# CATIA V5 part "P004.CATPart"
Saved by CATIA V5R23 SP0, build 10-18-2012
Part number: P004
Definition: Entretoise
Bounding box of the stored display mesh (mm): x -28 to 28, y -12 to 12, z -12 to 12
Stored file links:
  C:\wamp\www\COURS\CONCEPTION GMP1\TITRE 02-SEMESTRE 2\03-TP7-PRESSE MECANIQUE\eleve\P004.CATPart
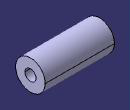
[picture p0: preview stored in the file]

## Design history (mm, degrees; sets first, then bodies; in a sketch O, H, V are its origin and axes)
Body1 (main body)
  Sketch1 on yz-plane, origin (0, 0, 0), H (0, 1, 0), V (0, 0, 1)
    circle A1 centre (0, 0) radius 12
    circle A2 centre (0, 0) radius 4.5
    radius A1 = 12
    radius A2 = 4.5
  Pad1: profile Sketch1, direction (1, 0, 0), length 28, mirrored extent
